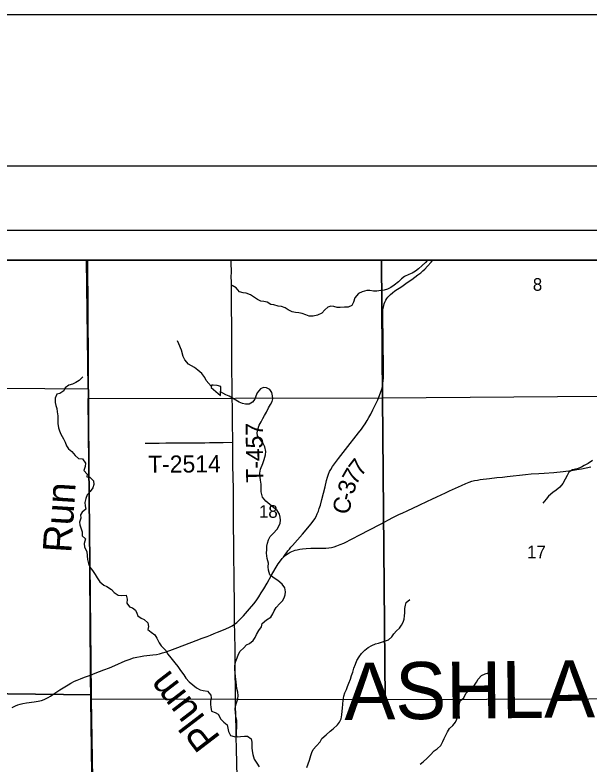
# Model space of a CAD drawing. Extents: x 0 to 34, y 0 to 22.
# Drawn here: x 3.831 to 5.733, y 19.516 to 22 of the extents above; entities that cross this region are included whole.
import ezdxf

# ---------------------------------------------------------------- set-up
doc = ezdxf.new("R2010")
doc.units = 0
for name, color, linetype in [('GM_X_County_Road_Text', 7, 'Continuous'), ('GM_X_Interchange_Ramps', 7, 'Continuous'), ('GM_X_Minor_River_Text', 7, 'Continuous'), ('GM_X_Rail_Line', 7, 'Continuous'), ('GM_X_Section_Text', 7, 'Continuous'), ('GM_X_State_Location', 7, 'Continuous'), ('GM_X_State_Route', 7, 'Continuous'), ('GM_X_Township_Road', 7, 'Continuous'), ('GM_X_Township_Road_Text', 7, 'Continuous'), ('GM_X_Township_Text', 7, 'Continuous'), ('SH_Border', 7, 'Continuous'), ('SH_Cut_Line', 7, 'Continuous'), ('SH_Data', 7, 'Continuous')]:
    doc.layers.add(name, color=color, linetype=linetype)

msp = doc.modelspace()

# ---------------------------------------------------------------- linework, layer by layer
at = {"layer": 'GM_X_County_Road_Text'}
for points in [[(5.1979, 21.1866), (5.1912, 21.1793), (5.1799, 21.1687), (5.1682, 21.1584), (5.158, 21.1504), (5.1467, 21.1435), (5.1361, 21.1389), (5.1221, 21.1328), (5.1115, 21.1251), (5.1017, 21.1149), (5.0877, 21.1042), (5.0764, 21.0965), (5.065, 21.0904), (5.0544, 21.0877), (5.0427, 21.0858), (5.0298, 21.0842), (5.0184, 21.0846), (5.0063, 21.0864), (4.9968, 21.0868), (4.9813, 21.0821), (4.9692, 21.0764), (4.9567, 21.0616), (4.953, 21.0479), (4.9466, 21.0361), (4.9353, 21.0315), (4.9231, 21.0307), (4.9084, 21.0295), (4.8989, 21.0298), (4.8875, 21.0328), (4.8777, 21.0339), (4.8671, 21.0312), (4.8572, 21.0225), (4.8482, 21.0111), (4.8331, 21.0045), (4.8194, 21.0007), (4.8054, 21.0014), (4.7952, 21.0059), (4.7826, 21.0104), (4.7716, 21.0119), (4.7603, 21.0134), (4.7493, 21.016), (4.7363, 21.022), (4.7257, 21.0288), (4.7136, 21.0337), (4.7029, 21.034), (4.6889, 21.0385), (4.679, 21.04), (4.6661, 21.0479), (4.6555, 21.0502), (4.6453, 21.0509), (4.6346, 21.0565), (4.6251, 21.0633), (4.6111, 21.072), (4.5966, 21.078), (4.5868, 21.0784), (4.5754, 21.0818), (4.564, 21.095), (4.5507, 21.1029)], [(4.4815, 20.7693), (4.4645, 20.7876), (4.4599, 20.7978), (4.4503, 20.8111), (4.4366, 20.8224), (4.4256, 20.8315), (4.4157, 20.8364), (4.4059, 20.8424), (4.3937, 20.8564), (4.3887, 20.8678), (4.3826, 20.889), (4.3741, 20.9095), (4.3695, 20.9197)], [(4.0559, 20.7997), (4.0442, 20.7883), (4.0321, 20.781), (4.0219, 20.776), (4.009, 20.7726), (3.9973, 20.7638), (3.9928, 20.7532), (3.9799, 20.7452), (3.9701, 20.7425), (3.9637, 20.7295), (3.9641, 20.7147), (3.9668, 20.7045), (3.9695, 20.6946), (3.9711, 20.6836), (3.9727, 20.6711), (3.9731, 20.659), (3.9735, 20.6457), (3.9751, 20.6309), (3.9786, 20.621), (3.9828, 20.6104), (3.9919, 20.5949), (3.9977, 20.5835), (4.0019, 20.571), (4.0087, 20.5608), (4.0194, 20.5525), (4.0301, 20.5393), (4.0411, 20.5287), (4.0544, 20.5276), (4.065, 20.514), (4.0636, 20.503), (4.0594, 20.4897), (4.0701, 20.4776), (4.069, 20.4681), (4.0785, 20.467), (4.091, 20.4556), (4.0919, 20.4427), (4.0893, 20.4325), (4.0802, 20.4195), (4.0704, 20.4085), (4.0663, 20.3971), (4.0629, 20.383), (4.0641, 20.372), (4.0657, 20.361), (4.054, 20.3515), (4.0476, 20.342), (4.0491, 20.3314), (4.045, 20.3185), (4.0458, 20.309), (4.05, 20.2961), (4.0531, 20.2859), (4.0539, 20.273), (4.0646, 20.2624), (4.0601, 20.2479), (4.0617, 20.235), (4.0689, 20.2203), (4.0705, 20.2062), (4.0717, 20.1941), (4.0748, 20.1808), (4.0794, 20.1687), (4.0874, 20.1581), (4.0969, 20.1445), (4.103, 20.1331), (4.1125, 20.1206), (4.1255, 20.1089), (4.1353, 20.1048), (4.1506, 20.095), (4.1593, 20.0851), (4.1734, 20.0761), (4.1855, 20.0754), (4.1991, 20.0758), (4.203, 20.0625), (4.2015, 20.0492), (4.2103, 20.0375), (4.2205, 20.0345), (4.2308, 20.0262), (4.2343, 20.0167), (4.2377, 20.0072), (4.2487, 19.9997), (4.2586, 19.9948), (4.2715, 19.9838), (4.2735, 19.9721), (4.2716, 19.9622), (4.2823, 19.9531), (4.2944, 19.9441), (4.3013, 19.9331), (4.3093, 19.9183), (4.3151, 19.9077), (4.3303, 19.8926), (4.3379, 19.8809), (4.3478, 19.868), (4.3611, 19.8521), (4.3707, 19.8393), (4.3798, 19.826), (4.3901, 19.8116), (4.3974, 19.801), (4.4084, 19.7882), (4.4198, 19.7787), (4.4324, 19.7689), (4.4449, 19.7621), (4.4548, 19.7603), (4.4684, 19.7573)], [(4.6643, 20.7633), (4.6544, 20.7644), (4.6442, 20.7606), (4.6337, 20.7469), (4.6288, 20.7355), (4.6254, 20.7256), (4.6175, 20.7161), (4.6065, 20.7092), (4.5948, 20.7091), (4.5845, 20.7114), (4.5739, 20.7163), (4.5625, 20.7227), (4.5519, 20.7295), (4.5405, 20.7363), (4.5298, 20.7404), (4.5123, 20.7508)], [(4.566, 19.606), (4.5653, 19.6153), (4.5652, 19.626), (4.5656, 19.6354), (4.5663, 19.6457), (4.5658, 19.6609), (4.5628, 19.6749), (4.5612, 19.6874), (4.5608, 19.6984), (4.5622, 19.7079), (4.5648, 19.7189), (4.569, 19.7318), (4.5704, 19.7432), (4.5692, 19.7542), (4.5665, 19.7664), (4.5646, 19.7774), (4.5634, 19.7876), (4.5614, 19.8058), (4.5603, 19.8187), (4.5594, 19.8305), (4.5594, 19.8415), (4.5631, 19.8574), (4.5669, 19.8685), (4.5717, 19.8806), (4.577, 19.8901), (4.5898, 19.9019), (4.5985, 19.9115), (4.6084, 19.916), (4.6204, 19.9256), (4.6272, 19.9359), (4.6313, 19.9461), (4.6393, 19.959), (4.6483, 19.9708), (4.6505, 19.9826), (4.6649, 19.9937), (4.6789, 20.0028), (4.6849, 20.0139), (4.6901, 20.0241), (4.6962, 20.0348), (4.709, 20.0481), (4.7169, 20.0576), (4.7229, 20.0671), (4.7267, 20.0774), (4.7278, 20.0869), (4.7254, 20.1002), (4.7159, 20.113), (4.7022, 20.1244), (4.6897, 20.1319), (4.6756, 20.1436), (4.6706, 20.1588), (4.6702, 20.1698), (4.6705, 20.1816), (4.6663, 20.1971), (4.6643, 20.2157), (4.665, 20.2271), (4.6657, 20.2388), (4.6672, 20.2487), (4.6706, 20.2597), (4.677, 20.2704), (4.6864, 20.2807), (4.6996, 20.2948), (4.7056, 20.3046), (4.7098, 20.3149), (4.7105, 20.3252), (4.7097, 20.3346), (4.7077, 20.3449), (4.6994, 20.3566), (4.6891, 20.3653), (4.6758, 20.3766), (4.6621, 20.3883), (4.6514, 20.4012), (4.6472, 20.419), (4.6464, 20.4289), (4.6463, 20.4437), (4.6447, 20.4577), (4.6436, 20.4672), (4.6424, 20.4801), (4.645, 20.4934), (4.6517, 20.5124), (4.6566, 20.5261), (4.6611, 20.5409), (4.6621, 20.5519), (4.659, 20.5682), (4.6537, 20.5792), (4.6453, 20.5902), (4.635, 20.6042), (4.6338, 20.6148), (4.6361, 20.6251), (4.6406, 20.6399), (4.6462, 20.6505), (4.6522, 20.6623), (4.6579, 20.6722), (4.6639, 20.6832), (4.6714, 20.6969), (4.6778, 20.7083), (4.6827, 20.7178), (4.6853, 20.7273), (4.6845, 20.7368), (4.6822, 20.7478), (4.6753, 20.7577), (4.6643, 20.7633)], [(5.7443, 20.523), (5.7307, 20.5123), (5.7174, 20.5062), (5.7076, 20.5004), (5.6936, 20.4951), (5.6785, 20.4916), (5.6664, 20.484), (5.6611, 20.4726), (5.6543, 20.4612), (5.6461, 20.4463), (5.6363, 20.4338), (5.6246, 20.4242), (5.6132, 20.4166), (5.5992, 20.4044), (5.5906, 20.3941), (5.58, 20.3808)], [(4.7981, 19.505), (4.8026, 19.5164), (4.8067, 19.5286), (4.8112, 19.5445), (4.8141, 19.554), (4.8194, 19.5639), (4.8303, 19.5765), (4.8417, 19.5898), (4.8481, 19.6005), (4.8617, 19.6127), (4.8756, 19.6245), (4.8858, 19.6329), (4.8998, 19.6458), (4.9066, 19.6553), (4.9115, 19.6656), (4.9144, 19.6796), (4.9155, 19.6914), (4.9162, 19.7009), (4.9173, 19.7142), (4.9188, 19.7282), (4.9206, 19.7408), (4.924, 19.7518), (4.9292, 19.7628), (4.933, 19.7734), (4.9371, 19.7837), (4.9427, 19.7978), (4.9461, 19.8092), (4.9502, 19.8209), (4.954, 19.8335), (4.9588, 19.8468), (4.9641, 19.859), (4.9712, 19.8715), (4.9795, 19.8825), (4.9897, 19.8936), (5.0014, 19.9027), (5.0135, 19.9096), (5.0256, 19.9142), (5.0355, 19.9173), (5.0483, 19.9211), (5.0589, 19.9242), (5.0691, 19.928), (5.0797, 19.9379), (5.0861, 19.9478), (5.0952, 19.9577), (5.105, 19.9661), (5.1114, 19.976), (5.1174, 19.9867), (5.1204, 19.9965), (5.1215, 20.0072), (5.1222, 20.017), (5.1229, 20.0322), (5.1244, 20.0425), (5.1274, 20.052), (5.1398, 20.0615)], [(5.1736, 19.5159), (5.1834, 19.5228), (5.1962, 19.535), (5.2064, 19.546), (5.2204, 19.5594), (5.2302, 19.567), (5.2423, 19.5773), (5.2491, 19.5906), (5.2532, 19.6008), (5.2581, 19.6119), (5.2637, 19.6233), (5.2712, 19.6343), (5.2814, 19.6438), (5.2905, 19.6553), (5.2946, 19.6651), (5.2972, 19.6762), (5.2991, 19.6883), (5.3005, 19.6989), (5.3024, 19.7118), (5.3061, 19.7251), (5.3178, 19.7354), (5.3246, 19.7503), (5.3382, 19.7628), (5.3518, 19.7739), (5.36, 19.7872), (5.3657, 19.7971), (5.3766, 19.8093), (5.3887, 19.815), (5.4001, 19.8185)], [(4.4684, 19.7573), (4.4802, 19.7448), (4.4814, 19.7353), (4.4788, 19.7243), (4.4792, 19.7144), (4.48, 19.7034), (4.4827, 19.6913), (4.4945, 19.6872), (4.5044, 19.6815), (4.5128, 19.6648), (4.523, 19.6554), (4.5337, 19.6456), (4.536, 19.6346), (4.5383, 19.624), (4.5452, 19.6107), (4.5574, 19.607), (4.5672, 19.6058), (4.5782, 19.607), (4.5915, 19.609), (4.6009, 19.6083), (4.6135, 19.6), (4.6154, 19.589), (4.6158, 19.5795), (4.6163, 19.5696), (4.6174, 19.5597), (4.619, 19.548), (4.6232, 19.5324), (4.632, 19.5192), (4.6396, 19.5071)]]:
    msp.add_lwpolyline(points, dxfattribs=at)
at = {"layer": 'GM_X_Interchange_Ramps'}
for points in [[(4.5527, 20.5829), (4.5525, 20.6054), (4.552, 20.6302), (4.5516, 20.6706), (4.5514, 20.6955), (4.551, 20.7328), (4.551, 20.7452), (4.5506, 20.7607), (4.5504, 20.7652), (4.5502, 20.7818), (4.5499, 20.8127), (4.5495, 20.8415), (4.5498, 20.8751), (4.55, 20.9034), (4.5498, 20.9149), (4.5496, 20.9359), (4.5493, 20.9594), (4.549, 20.9848), (4.5486, 21.0143), (4.5485, 21.0215), (4.5483, 21.0492), (4.5481, 21.0812), (4.5479, 21.1144), (4.5477, 21.1333), (4.5479, 21.1458), (4.5476, 21.1799), (4.5475, 21.1866)], [(4.262, 20.5801), (4.2728, 20.5804), (4.2876, 20.5804), (4.309, 20.5804), (4.3304, 20.5808), (4.358, 20.5809), (4.3794, 20.5811), (4.3917, 20.5811), (4.401, 20.581), (4.4071, 20.581), (4.4379, 20.5814), (4.4606, 20.5817), (4.4758, 20.5818), (4.4873, 20.582), (4.4965, 20.5823), (4.5213, 20.5825), (4.5527, 20.5829)], [(4.5589, 19.9803), (4.5586, 19.9899), (4.5588, 20.0013), (4.5586, 20.0281), (4.5582, 20.0693), (4.5577, 20.1012), (4.5573, 20.1257), (4.5574, 20.1417), (4.5571, 20.1539), (4.5563, 20.1913), (4.5561, 20.2096), (4.556, 20.2347), (4.5559, 20.2595), (4.5554, 20.2935), (4.555, 20.3307), (4.5547, 20.3741), (4.5547, 20.4081), (4.5545, 20.4267), (4.5536, 20.4701), (4.5531, 20.5042), (4.553, 20.5476), (4.5527, 20.5829)]]:
    msp.add_lwpolyline(points, dxfattribs=at)
at = {"layer": 'GM_X_Minor_River_Text'}
for points in [[(4.5131, 20.768), (4.5005, 20.771), (4.4876, 20.7729), (4.4823, 20.7729), (4.4805, 20.7649), (4.5117, 20.7377)], [(4.5117, 20.7377), (4.5131, 20.768)]]:
    msp.add_lwpolyline(points, dxfattribs=at)
at = {"layer": 'GM_X_State_Route'}
for points in [[(4.068, 21.1866), (3.0663, 21.1866), (3.0692, 20.7682), (4.0731, 20.7603)], [(5.0449, 21.1866), (4.068, 21.1866), (4.0731, 20.7603), (4.0736, 20.7285), (5.0487, 20.73)], [(8.6602, 18.8038), (8.6602, 21.1866), (4.0708, 21.1866), (4.0805, 19.8173), (4.0805, 19.8117), (4.0945, 18.7432), (4.5791, 18.7479), (5.5804, 18.7605), (5.5812, 18.7605), (6.0902, 18.7638), (7.082, 18.7532), (7.9519, 18.7787), (8.0539, 18.7796), (8.5878, 18.803)], [(6.0868, 21.1866), (5.0449, 21.1866), (5.0487, 20.73), (6.064, 20.7377)], [(3.0692, 20.7682), (4.0731, 20.7603), (4.0736, 20.7285), (4.0835, 19.7451), (3.0705, 19.7579)], [(4.0736, 20.7285), (5.0487, 20.73), (5.0579, 19.7292), (4.0839, 19.7307), (4.0835, 19.7451)], [(5.0487, 20.73), (6.064, 20.7377), (6.0697, 19.7327), (5.0579, 19.7292)], [(3.0705, 19.7579), (4.0835, 19.7451), (4.0839, 19.7307), (4.0999, 18.7413), (3.0743, 18.754)]]:
    msp.add_lwpolyline(points, close=True, dxfattribs=at)
at = {"layer": 'GM_X_Township_Road'}
for points in [[(4.7207, 20.2025), (4.7272, 20.2117), (4.7314, 20.2174), (4.7356, 20.2227), (4.7407, 20.2289), (4.7455, 20.2348), (4.7506, 20.2405), (4.7669, 20.2593), (4.7832, 20.278), (4.8014, 20.2992), (4.8113, 20.3113), (4.8188, 20.3213), (4.824, 20.3291), (4.8287, 20.3372), (4.8327, 20.3456), (4.8362, 20.3543), (4.8393, 20.3631), (4.8429, 20.375), (4.8478, 20.393), (4.8533, 20.414), (4.8584, 20.435), (4.8635, 20.456), (4.8664, 20.4678), (4.8696, 20.4774), (4.8731, 20.4858), (4.8776, 20.4933), (4.8833, 20.503), (4.8892, 20.5115), (4.9029, 20.529), (4.9264, 20.5588), (4.9694, 20.614), (4.9789, 20.6263), (4.9862, 20.6364), (4.9914, 20.6441), (4.998, 20.6547), (5.0039, 20.6655), (5.01, 20.6768), (5.0169, 20.6904), (5.0329, 20.724), (5.039, 20.7383), (5.0434, 20.75), (5.0461, 20.759), (5.0484, 20.7681), (5.05, 20.7774), (5.0512, 20.7866), (5.0516, 20.7957), (5.0518, 20.8048), (5.0516, 20.8154), (5.0515, 20.8346), (5.0515, 20.8609), (5.0507, 20.8854), (5.051, 20.9164), (5.0504, 20.9442), (5.0496, 20.9785), (5.0495, 20.9972), (5.0497, 21.0126), (5.0503, 21.0219), (5.0516, 21.031), (5.0529, 21.037), (5.0541, 21.0424), (5.0563, 21.0482), (5.0595, 21.0543), (5.0629, 21.0595), (5.0664, 21.0643), (5.0703, 21.0688), (5.0751, 21.0733), (5.0822, 21.0791), (5.0898, 21.0847), (5.113, 21.0998), (5.1306, 21.1125), (5.1458, 21.1233), (5.1659, 21.1378), (5.1756, 21.1452), (5.1828, 21.1512), (5.1894, 21.1574), (5.1979, 21.1667), (5.2104, 21.1806), (5.2158, 21.1866)], [(4.7207, 20.2025), (4.7258, 20.2072), (4.7305, 20.2108), (4.7358, 20.2142), (4.7427, 20.2181), (4.7488, 20.2211), (4.7539, 20.223), (4.7597, 20.225), (4.7656, 20.2267), (4.7746, 20.2286), (4.7838, 20.2299), (4.7962, 20.2308), (4.8116, 20.2314), (4.824, 20.2316), (4.8488, 20.2319), (4.8612, 20.2324), (4.8705, 20.2333), (4.8797, 20.2346), (4.8889, 20.2366), (4.8974, 20.2391), (4.9084, 20.2435), (4.9207, 20.2489), (4.9507, 20.2641), (4.9714, 20.2751), (5.0417, 20.3119), (5.083, 20.3333), (5.1024, 20.343), (5.1165, 20.3496), (5.1306, 20.3561), (5.1699, 20.3745), (5.1981, 20.3874), (5.2122, 20.3939), (5.229, 20.4019), (5.243, 20.4086), (5.257, 20.4151), (5.2711, 20.4217), (5.2908, 20.431), (5.3104, 20.4402), (5.3247, 20.4464), (5.3362, 20.4508), (5.345, 20.4537), (5.354, 20.456), (5.3631, 20.4578), (5.3722, 20.4592), (5.4029, 20.4629), (5.4274, 20.4658), (5.4459, 20.4678), (5.4613, 20.4696), (5.523, 20.4765), (5.5415, 20.4781), (5.5663, 20.4795), (5.5849, 20.4808), (5.6159, 20.4833), (5.6468, 20.4863), (5.6745, 20.4897), (5.693, 20.4925), (5.7083, 20.4953), (5.7387, 20.5013)], [(4.5589, 19.9803), (4.5657, 19.9855), (4.5704, 19.9896), (4.5771, 19.9961), (4.5877, 20.0076), (4.6081, 20.031), (4.622, 20.0477), (4.6297, 20.0575), (4.6386, 20.0702), (4.6471, 20.0833), (4.6552, 20.0966), (4.6661, 20.1154), (4.6814, 20.1424), (4.6933, 20.1636), (4.7035, 20.1798), (4.7103, 20.1902), (4.7161, 20.1978), (4.7207, 20.2025)], [(4.0808, 19.8111), (4.0962, 19.817), (4.1112, 19.8224), (4.1259, 19.828), (4.1437, 19.8351), (4.1619, 19.8431), (4.1964, 19.8578), (4.2089, 19.8627), (4.2238, 19.8678), (4.2349, 19.8705), (4.2468, 19.8731), (4.2575, 19.8744), (4.2875, 19.878), (4.2999, 19.8797), (4.3104, 19.8819), (4.3194, 19.8844), (4.3283, 19.8872), (4.3436, 19.8927), (4.3703, 19.9027), (4.4314, 19.9256), (4.4517, 19.9334), (4.4675, 19.9394), (4.4791, 19.9439), (4.4906, 19.9485), (4.5021, 19.9532), (4.5222, 19.9615), (4.5392, 19.9691), (4.5503, 19.9748), (4.5583, 19.9798), (4.5589, 19.9803)], [(4.5668, 19.4747), (4.566, 19.5182), (4.5652, 19.5679), (4.5642, 19.6052), (4.5635, 19.6363), (4.563, 19.6674), (4.5622, 19.7202), (4.5618, 19.7481), (4.5613, 19.776), (4.5608, 19.8102), (4.5604, 19.8693), (4.5601, 19.9065), (4.5596, 19.9376), (4.5593, 19.9531), (4.5589, 19.9803)], [(3.8214, 19.7037), (3.8322, 19.7095), (3.8405, 19.7129), (3.8478, 19.7151), (3.8568, 19.7171), (3.8692, 19.7188), (3.8948, 19.7221), (3.9078, 19.7244), (3.9184, 19.727), (3.9274, 19.7301), (3.9347, 19.733), (3.9411, 19.7362), (3.9487, 19.7408), (3.9568, 19.7463), (3.98, 19.7616), (3.9961, 19.7721), (4.0067, 19.7788), (4.0164, 19.7843), (4.0281, 19.7904), (4.0372, 19.7944), (4.0476, 19.7991), (4.0616, 19.8039), (4.0743, 19.8086), (4.0808, 19.8111)]]:
    msp.add_lwpolyline(points, dxfattribs=at)
at = {"layer": 'SH_Border'}
msp.add_lwpolyline([(1.5, 21.5), (33.5, 21.5), (33.5, 0.5), (1.5, 0.5)], close=True, dxfattribs=at)
at = {"layer": 'SH_Cut_Line'}
msp.add_lwpolyline([(0, 0), (34, 0), (34, 22), (0, 22)], close=True, dxfattribs=at)
at = {"layer": 'SH_Data'}
for points in [[(1.7602, 21.2866), (8.7602, 21.2866), (8.7602, 14.2866), (1.7602, 14.2866)], [(1.8602, 21.1866), (8.6602, 21.1866), (8.6602, 14.3866), (1.8602, 14.3866)]]:
    msp.add_lwpolyline(points, close=True, dxfattribs=at)

# ---------------------------------------------------------------- texts
at = {"layer": 'GM_X_Rail_Line'}
msp.add_text('ASHLAND COUNTY', height=0.189394, rotation=0.605, dxfattribs=at).set_placement((4.9228, 19.6623))
at = {"layer": 'GM_X_Section_Text'}
for s, rotation, p in [('7', 52.9001, (4.9772, 20.4667)), ('7', 60.168, (4.9609, 20.4379)), ('3', 74.8681, (4.9532, 20.4077)), ('C', 75.587, (4.9358, 20.3401)), ('-', 75.5151, (4.9474, 20.3853))]:
    msp.add_text(s, height=0.0568, rotation=rotation, dxfattribs=at).set_placement(p)
at = {"layer": 'GM_X_State_Location'}
for s, height, p in [('8', 0.0419, (5.5468, 21.0854)), ('18', 0.04186, (4.6393, 20.3325)), ('17', 0.04186, (5.5276, 20.1984))]:
    msp.add_text(s, height=height, rotation=0, dxfattribs=at).set_placement(p)
at = {"layer": 'GM_X_Township_Road_Text'}
for s, rotation, p in [('Run', 86.2813, (4.0173, 20.2148)), ('Plum', 127.4935, (4.5147, 19.6038))]:
    msp.add_text(s, height=0.09472, rotation=rotation, dxfattribs=at).set_placement(p)
at = {"layer": 'GM_X_Township_Text'}
for s, rotation, p in [('T-457', 90.5659, (4.654, 20.449)), ('T-2514', 0.4632, (4.2723, 20.4817))]:
    msp.add_text(s, height=0.05682, rotation=rotation, dxfattribs=at).set_placement(p)

doc.saveas('drawing.dxf')
